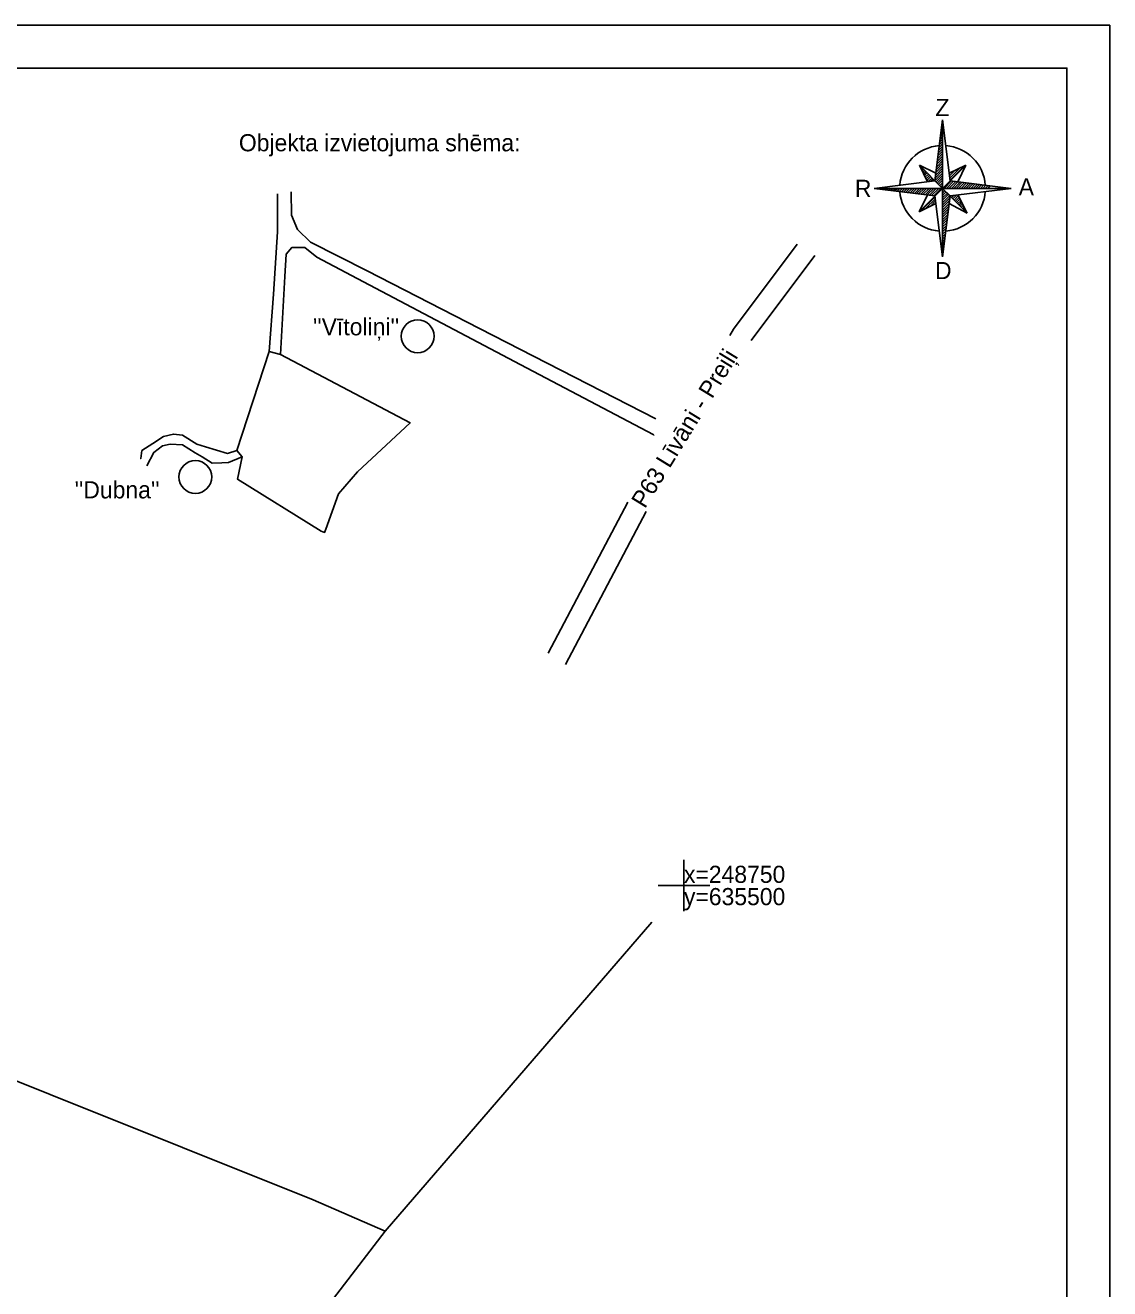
# Model space of a CAD drawing. Extents: x 635228 to 635525, y 248590 to 248800.
# Drawn here: x 635461.6 to 635524.8, y 248726.5 to 248800.2 of the extents above; entities that cross this region are included whole.
import ezdxf

# ---------------------------------------------------------------- set-up
doc = ezdxf.new("R2010")
doc.units = 0
for name, color, linetype in [('GEOD_ELEM_####_####_#', 7, 'Continuous'), ('GEOD_KORD_####_TKST_#', 7, 'Continuous'), ('RAMI_PLAN_####_TKST_#', 7, 'Continuous'), ('ROBZ_IERR_####_####_#', 7, 'Continuous')]:
    doc.layers.add(name, color=color, linetype=linetype)

msp = doc.modelspace()

# ---------------------------------------------------------------- linework, layer by layer
at = {"layer": 'GEOD_ELEM_####_####_#'}
for p, q in [((635500, 248751.5), (635500, 248750)), ((635498.5, 248750), (635500, 248750)), ((635500, 248750), (635500, 248748.5)), ((635500, 248750), (635501.5, 248750))]:
    msp.add_line(p, q, dxfattribs=at)
at = {"layer": 'RAMI_PLAN_####_TKST_#'}
for p, q in [((635515.086, 248794.663), (635514.644, 248791.105)), ((635515.086, 248794.663), (635515.086, 248790.663)), ((635515.528, 248791.105), (635515.086, 248794.663)), ((635514.966, 248793.701), (635515.086, 248793.821)), ((635514.986, 248793.863), (635515.086, 248793.962)), ((635515.006, 248794.024), (635515.086, 248794.104)), ((635515.027, 248794.186), (635515.086, 248794.245)), ((635514.866, 248792.894), (635515.086, 248793.114)), ((635514.886, 248793.055), (635515.086, 248793.255)), ((635514.906, 248793.217), (635515.086, 248793.397)), ((635514.926, 248793.378), (635515.086, 248793.538)), ((635514.946, 248793.54), (635515.086, 248793.679)), ((635514.746, 248791.925), (635515.086, 248792.265)), ((635514.766, 248792.087), (635515.086, 248792.407)), ((635514.786, 248792.248), (635515.086, 248792.548)), ((635514.806, 248792.41), (635515.086, 248792.689)), ((635514.826, 248792.571), (635515.086, 248792.831)), ((635514.846, 248792.732), (635515.086, 248792.972)), ((635513.733, 248792.016), (635515.086, 248790.663)), ((635514.699, 248791.547), (635513.733, 248792.016)), ((635513.733, 248792.016), (635514.202, 248791.05)), ((635513.753, 248791.976), (635513.763, 248791.986)), ((635513.799, 248791.88), (635513.834, 248791.915)), ((635513.845, 248791.785), (635513.904, 248791.845)), ((635513.891, 248791.69), (635513.975, 248791.774)), ((635513.938, 248791.595), (635514.046, 248791.703)), ((635513.984, 248791.5), (635514.117, 248791.632)), ((635514.03, 248791.404), (635514.187, 248791.562)), ((635514.645, 248791.118), (635515.086, 248791.558)), ((635514.665, 248791.279), (635515.086, 248791.7)), ((635514.686, 248791.441), (635515.086, 248791.841)), ((635514.706, 248791.602), (635515.086, 248791.982)), ((635514.726, 248791.764), (635515.086, 248792.124)), ((635515.086, 248790.663), (635516.439, 248792.016)), ((635515.473, 248791.547), (635516.439, 248792.016)), ((635515.476, 248791.519), (635515.535, 248791.577)), ((635515.492, 248791.393), (635515.81, 248791.711)), ((635515.508, 248791.267), (635516.085, 248791.844)), ((635515.523, 248791.141), (635516.36, 248791.978)), ((635516.439, 248792.016), (635515.97, 248791.05)), ((635514.644, 248791.105), (635511.086, 248790.663)), ((635514.076, 248791.309), (635514.258, 248791.491)), ((635514.122, 248791.214), (635514.329, 248791.42)), ((635514.169, 248791.119), (635514.399, 248791.35)), ((635514.247, 248791.056), (635514.47, 248791.279)), ((635514.408, 248791.076), (635514.541, 248791.208)), ((635514.57, 248791.096), (635514.611, 248791.137)), ((635514.644, 248791.105), (635515.086, 248790.663)), ((635514.709, 248791.04), (635515.086, 248791.417)), ((635514.78, 248790.969), (635515.086, 248791.275)), ((635514.85, 248790.898), (635515.086, 248791.134)), ((635514.921, 248790.828), (635515.086, 248790.992)), ((635514.992, 248790.757), (635515.086, 248790.851)), ((635515.086, 248790.663), (635515.528, 248791.105)), ((635515.172, 248790.663), (635515.605, 248791.096)), ((635515.314, 248790.663), (635515.73, 248791.08)), ((635515.455, 248790.663), (635515.856, 248791.064)), ((635519.086, 248790.663), (635515.528, 248791.105)), ((635515.597, 248790.663), (635515.982, 248791.049)), ((635515.738, 248790.663), (635516.108, 248791.033)), ((635515.879, 248790.663), (635516.234, 248791.017)), ((635516.021, 248790.663), (635516.359, 248791.002)), ((635516.162, 248790.663), (635516.485, 248790.986)), ((635516.304, 248790.663), (635516.611, 248790.971)), ((635516.445, 248790.663), (635516.737, 248790.955)), ((635516.587, 248790.663), (635516.863, 248790.939)), ((635516.728, 248790.663), (635516.988, 248790.924)), ((635516.869, 248790.663), (635517.114, 248790.908)), ((635517.011, 248790.663), (635517.24, 248790.892)), ((635517.152, 248790.663), (635517.366, 248790.877)), ((635517.294, 248790.663), (635517.492, 248790.861)), ((635517.435, 248790.663), (635517.617, 248790.846)), ((635517.576, 248790.663), (635517.743, 248790.83)), ((635517.718, 248790.663), (635517.869, 248790.814)), ((635511.086, 248790.663), (635519.086, 248790.663)), ((635511.086, 248790.663), (635514.644, 248790.221)), ((635511.175, 248790.652), (635511.186, 248790.663)), ((635511.3, 248790.637), (635511.327, 248790.663)), ((635511.426, 248790.621), (635511.468, 248790.663)), ((635511.552, 248790.605), (635511.61, 248790.663)), ((635511.678, 248790.59), (635511.751, 248790.663)), ((635511.804, 248790.574), (635511.893, 248790.663)), ((635511.929, 248790.558), (635512.034, 248790.663)), ((635512.055, 248790.543), (635512.176, 248790.663)), ((635512.181, 248790.527), (635512.317, 248790.663)), ((635512.307, 248790.512), (635512.458, 248790.663)), ((635512.433, 248790.496), (635512.6, 248790.663)), ((635512.558, 248790.48), (635512.741, 248790.663)), ((635512.684, 248790.465), (635512.883, 248790.663)), ((635512.81, 248790.449), (635513.024, 248790.663)), ((635512.936, 248790.433), (635513.166, 248790.663)), ((635513.062, 248790.418), (635513.307, 248790.663)), ((635513.187, 248790.402), (635513.448, 248790.663)), ((635513.313, 248790.387), (635513.59, 248790.663)), ((635513.439, 248790.371), (635513.731, 248790.663)), ((635513.565, 248790.355), (635513.873, 248790.663)), ((635513.691, 248790.34), (635514.014, 248790.663)), ((635513.721, 248789.298), (635515.086, 248790.663)), ((635514.202, 248790.276), (635513.721, 248789.298)), ((635513.816, 248790.324), (635514.155, 248790.663)), ((635513.818, 248789.346), (635514.649, 248790.177)), ((635513.942, 248790.308), (635514.297, 248790.663)), ((635514.068, 248790.293), (635514.438, 248790.663)), ((635514.096, 248789.483), (635514.665, 248790.052)), ((635514.194, 248790.277), (635514.58, 248790.663)), ((635514.32, 248790.262), (635514.721, 248790.663)), ((635514.445, 248790.246), (635514.863, 248790.663)), ((635514.571, 248790.23), (635515.004, 248790.663)), ((635514.644, 248790.221), (635515.086, 248790.663)), ((635514.644, 248790.221), (635515.086, 248786.663)), ((635515.063, 248790.686), (635515.086, 248790.71)), ((635515.086, 248790.663), (635516.528, 248789.221)), ((635515.086, 248790.663), (635515.086, 248786.663)), ((635515.528, 248790.221), (635515.086, 248790.663)), ((635515.086, 248790.532), (635515.151, 248790.597)), ((635515.086, 248790.39), (635515.222, 248790.527)), ((635515.086, 248790.249), (635515.293, 248790.456)), ((635515.086, 248790.108), (635515.364, 248790.385)), ((635515.086, 248789.966), (635515.434, 248790.315)), ((635515.086, 248789.825), (635515.505, 248790.244)), ((635515.086, 248786.663), (635515.528, 248790.221)), ((635515.086, 248789.683), (635515.514, 248790.112)), ((635515.528, 248790.221), (635519.086, 248790.663)), ((635515.553, 248790.196), (635515.585, 248790.228)), ((635515.623, 248790.125), (635515.746, 248790.248)), ((635515.694, 248790.055), (635515.908, 248790.268)), ((635515.765, 248789.984), (635516, 248790.219)), ((635515.836, 248789.913), (635516.049, 248790.127)), ((635515.906, 248789.843), (635516.098, 248790.034)), ((635516.528, 248789.221), (635515.97, 248790.276)), ((635513.721, 248789.298), (635514.699, 248789.779)), ((635514.375, 248789.62), (635514.681, 248789.926)), ((635514.653, 248789.757), (635514.696, 248789.8)), ((635515.086, 248789.542), (635515.494, 248789.95)), ((635515.086, 248789.4), (635515.474, 248789.789)), ((635515.086, 248789.259), (635515.454, 248789.627)), ((635515.086, 248789.118), (635515.434, 248789.466)), ((635515.086, 248788.976), (635515.414, 248789.304)), ((635515.473, 248789.779), (635516.528, 248789.221)), ((635515.977, 248789.772), (635516.147, 248789.942)), ((635516.048, 248789.701), (635516.196, 248789.849)), ((635516.118, 248789.63), (635516.245, 248789.757)), ((635516.189, 248789.56), (635516.294, 248789.664)), ((635516.26, 248789.489), (635516.343, 248789.572)), ((635516.331, 248789.418), (635516.391, 248789.479)), ((635516.401, 248789.348), (635516.44, 248789.387)), ((635516.472, 248789.277), (635516.489, 248789.294)), ((635515.086, 248788.835), (635515.394, 248789.143)), ((635515.086, 248788.693), (635515.374, 248788.981)), ((635515.086, 248788.552), (635515.354, 248788.82)), ((635515.086, 248788.41), (635515.334, 248788.658)), ((635515.086, 248788.269), (635515.314, 248788.497)), ((635515.086, 248788.128), (635515.293, 248788.335)), ((635515.086, 248787.986), (635515.273, 248788.174)), ((635515.086, 248787.845), (635515.253, 248788.012)), ((635515.086, 248787.703), (635515.233, 248787.851)), ((635515.086, 248787.562), (635515.213, 248787.689)), ((635515.086, 248787.421), (635515.193, 248787.528)), ((635515.086, 248787.279), (635515.173, 248787.366)), ((635515.086, 248787.138), (635515.153, 248787.205)), ((635515.086, 248786.996), (635515.133, 248787.044)), ((635515.086, 248786.855), (635515.113, 248786.882)), ((635515.086, 248786.713), (635515.093, 248786.721))]:
    msp.add_line(p, q, dxfattribs=at)
for points in [[(635227.837, 248590.176), (635227.837, 248800.176), (635524.837, 248800.176), (635524.837, 248590.176)], [(635237.837, 248797.676), (635237.837, 248592.676), (635522.337, 248592.676), (635522.337, 248797.676)], [(635475.798, 248781.15), (635476.463, 248780.97), (635484.033, 248776.985), (635480.959, 248774.125), (635479.844, 248772.839), (635479.106, 248770.788), (635479.035, 248770.589), (635478.836, 248770.661), (635473.955, 248773.693), (635474.224, 248774.998), (635473.91, 248775.375)]]:
    msp.add_lwpolyline(points, close=True, dxfattribs=at)
for points in [[(635476.291, 248790.339), (635476.291, 248788.136), (635476.055, 248784.5), (635475.798, 248781.15)], [(635498.355, 248777.22), (635488.076, 248782.485), (635481.512, 248785.846), (635478.216, 248787.534), (635477.455, 248788.262), (635477.109, 248789.096), (635477.078, 248790.465)], [(635476.463, 248780.97), (635476.716, 248785.523), (635476.788, 248786.821), (635477.125, 248787.223), (635477.125, 248787.223), (635477.88, 248787.223), (635478.573, 248786.656), (635480.602, 248785.586), (635490.823, 248780.195), (635498.243, 248776.283), (635498.243, 248776.283)], [(635502.68, 248782.086), (635502.893, 248782.445), (635506.61, 248787.404)], [(635503.912, 248781.784), (635507.629, 248786.743)], [(635473.91, 248775.375), (635474.224, 248774.998), (635473.955, 248773.693), (635478.836, 248770.661), (635479.035, 248770.589), (635479.106, 248770.788), (635479.844, 248772.839), (635480.959, 248774.125), (635484.033, 248776.985), (635476.463, 248780.97), (635475.798, 248781.15), (635473.91, 248775.375)], [(635473.91, 248775.375), (635473.365, 248775.197), (635472.09, 248775.59), (635471.575, 248775.749), (635470.753, 248776.267), (635470.218, 248776.33), (635469.636, 248776.188), (635469.006, 248775.779), (635468.377, 248775.37), (635468.314, 248774.898), (635468.314, 248774.898)], [(635468.66, 248774.473), (635469.069, 248775.26), (635469.573, 248775.653), (635470.029, 248775.748), (635470.753, 248775.7), (635471.492, 248775.244), (635471.892, 248774.997), (635472.479, 248774.635), (635473.034, 248774.661), (635473.432, 248774.681), (635474.224, 248774.998)], [(635492.072, 248763.548), (635496.717, 248772.364)], [(635493.091, 248762.887), (635497.794, 248771.812)]]:
    msp.add_lwpolyline(points, dxfattribs=at)
for centre in [(635484.465, 248782.036), (635471.496, 248773.827)]:
    msp.add_circle(centre, 0.958, dxfattribs=at)
for start, end in [(94.29323, 175.70528), (4.29323, 85.70528), (184.29323, 265.70528), (274.29323, 355.70528)]:
    msp.add_arc((635515.086, 248790.663), 2.5, start, end, dxfattribs=at)
at = {"layer": 'ROBZ_IERR_####_####_#'}
for points in [[(635390.87, 248797.676), (635383.387, 248769.687), (635386.484, 248768.447), (635478.377, 248731.658), (635482.561, 248729.828), (635465.459, 248707.539), (635458.607, 248711.134), (635360.483, 248762.615), (635360.888, 248769.918), (635363.321, 248797.676)], [(635522.337, 248635.854), (635430.959, 248667.773), (635424.543, 248670.014), (635439.457, 248681.038), (635465.459, 248707.539), (635482.561, 248729.828), (635498.129, 248747.855)]]:
    msp.add_lwpolyline(points, dxfattribs=at)

# ---------------------------------------------------------------- texts
at = {"layer": 'GEOD_KORD_####_TKST_#'}
for s, p in [('x=248750', (635500, 248750.15)), ('y=635500', (635500, 248748.85))]:
    msp.add_text(s, height=1, dxfattribs=at).set_placement(p)
at = {"layer": 'RAMI_PLAN_####_TKST_#'}
for s, rotation, p in [('Z', 359.99925, (635514.668, 248794.88)), ('R', 359.99925, (635509.969, 248790.164)), ('A', 359.99925, (635519.526, 248790.253)), ('D', 359.99925, (635514.643, 248785.369)), ('P63 Līvāni - Preiļi', 58.54495, (635497.723, 248771.94))]:
    msp.add_text(s, height=1, rotation=rotation, dxfattribs=at).set_placement(p)
for s, p in [('Objekta izvietojuma shēma:', (635474.036, 248792.825)), ("''Vītoliņi''", (635478.354, 248782.091)), ("''Dubna''", (635464.451, 248772.579))]:
    msp.add_text(s, height=1, dxfattribs=at).set_placement(p)

doc.saveas('drawing.dxf')
